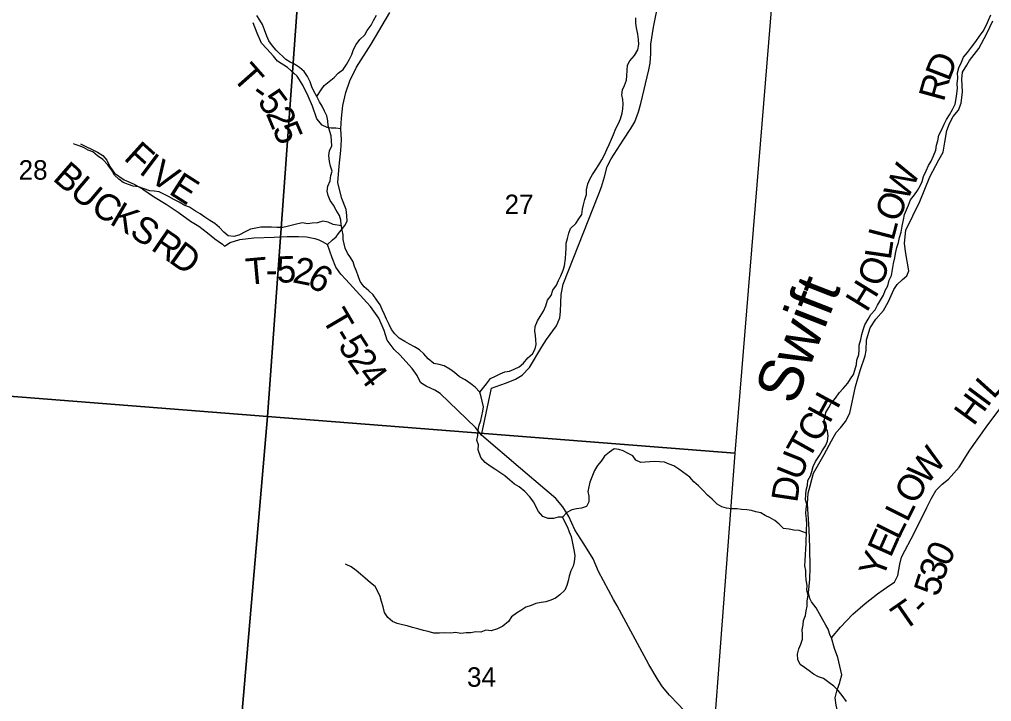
# Model space of a CAD drawing. Extents: x 1578669 to 1989827, y 208020 to 553079.
# Drawn here: x 1870195 to 1881237, y 380354 to 388101 of the extents above; entities that cross this region are included whole.
import ezdxf

# ---------------------------------------------------------------- set-up
doc = ezdxf.new("R2010")
doc.units = 0
for name, color, linetype in [('GM_X_Minor_River', 7, 'Continuous'), ('GM_X_Minor_River_Text', 7, 'Continuous'), ('GM_X_Section', 7, 'Continuous'), ('GM_X_Section_Text', 7, 'Continuous'), ('GM_X_State_Route', 7, 'Continuous'), ('GM_X_Township_Road', 7, 'Continuous'), ('GM_X_Township_Road_Text', 7, 'Continuous')]:
    doc.layers.add(name, color=color, linetype=linetype)

msp = doc.modelspace()

# ---------------------------------------------------------------- linework, layer by layer
at = {"layer": 'GM_X_Minor_River'}
for points in [[(1873498, 387392), (1873466, 387454), (1873428, 387508), (1873376, 387556), (1873320, 387592), (1873270, 387614), (1873220, 387646), (1873113, 387752), (1873071, 387802), (1873027, 387856), (1873005, 387910), (1872977, 387982), (1872957, 388042), (1872927, 388094), (1872891, 388146)], [(1873574, 387224), (1873622, 387300), (1873658, 387352), (1873714, 387394), (1873770, 387440), (1873816, 387490), (1873872, 387533), (1873911, 387589), (1873943, 387649), (1873971, 387703), (1873991, 387759), (1874021, 387815), (1874063, 387871), (1874119, 387925), (1874146, 387976), (1874190, 388034), (1874218, 388090), (1874250, 388150)], [(1879149, 382863), (1879179, 382917), (1879197, 382967), (1879211, 383023), (1879237, 383079), (1879283, 383147), (1879315, 383200), (1879350, 383258), (1879372, 383312), (1879380, 383372), (1879372, 383426), (1879346, 383482), (1879334, 383534), (1879346, 383588), (1879356, 383638), (1879389, 383694), (1879415, 383744), (1879463, 383801), (1879505, 383859), (1879551, 383909), (1879605, 383969), (1879635, 384019), (1879670, 384069), (1879684, 384119), (1879702, 384180), (1879706, 384232), (1879728, 384296), (1879732, 384346), (1879732, 384402), (1879752, 384464), (1879765, 384522), (1879779, 384576), (1879797, 384634), (1879837, 384695), (1879867, 384749), (1879917, 384801), (1879943, 384857), (1879975, 384911), (1880008, 384969), (1880030, 385021), (1880058, 385077), (1880076, 385138), (1880100, 385194), (1880114, 385262), (1880124, 385328), (1880137, 385394), (1880145, 385444), (1880161, 385510), (1880181, 385566), (1880191, 385624), (1880211, 385685), (1880223, 385753), (1880238, 385823), (1880250, 385887), (1880272, 385937), (1880294, 385993), (1880318, 386053), (1880362, 386107), (1880396, 386158), (1880428, 386212), (1880449, 386262), (1880463, 386318), (1880493, 386382), (1880521, 386442), (1880551, 386492), (1880579, 386550), (1880605, 386615), (1880612, 386671), (1880628, 386723), (1880640, 386787), (1880674, 386851), (1880700, 386911), (1880724, 386965), (1880760, 387019), (1880793, 387078), (1880823, 387138), (1880837, 387202), (1880843, 387254), (1880849, 387320), (1880845, 387370), (1880853, 387434), (1880849, 387496), (1880866, 387552), (1880894, 387614), (1880920, 387671), (1880964, 387725), (1881008, 387785), (1881060, 387849), (1881102, 387911), (1881141, 387967), (1881181, 388038), (1881201, 388094), (1881229, 388154)], [(1875423, 383868), (1875499, 383964), (1875544, 384022), (1875602, 384051), (1875654, 384075), (1875708, 384097), (1875760, 384105), (1875814, 384127), (1875870, 384157), (1875922, 384197), (1875970, 384257), (1876024, 384304), (1876053, 384358), (1876063, 384410), (1876061, 384462), (1876057, 384512), (1876051, 384562), (1876055, 384614), (1876079, 384678), (1876111, 384728), (1876148, 384789), (1876174, 384849), (1876192, 384913), (1876234, 384967), (1876254, 385027), (1876294, 385083), (1876318, 385137), (1876344, 385189), (1876373, 385252), (1876387, 385302), (1876397, 385386), (1876403, 385446), (1876405, 385502), (1876405, 385558), (1876419, 385614), (1876436, 385672), (1876456, 385726), (1876514, 385785), (1876548, 385835), (1876584, 385887), (1876592, 385945), (1876602, 385995), (1876618, 386055), (1876635, 386111), (1876637, 386167), (1876653, 386235), (1876673, 386286), (1876703, 386340), (1876743, 386398), (1876775, 386448), (1876812, 386508), (1876842, 386562), (1876866, 386624), (1876892, 386682), (1876920, 386739), (1876942, 386793), (1876970, 386863), (1877000, 386917), (1877023, 386973), (1877043, 387035), (1877049, 387087), (1877051, 387137), (1877049, 387193), (1877037, 387245), (1877045, 387300), (1877067, 387352), (1877092, 387412), (1877096, 387462), (1877100, 387522), (1877102, 387580), (1877128, 387632), (1877182, 387690), (1877218, 387754), (1877231, 387817), (1877227, 387873), (1877219, 387935), (1877205, 388007), (1877197, 388057), (1877195, 388117)], [(1876365, 382449), (1876313, 382447), (1876262, 382433), (1876202, 382431), (1876142, 382455), (1876091, 382513), (1876063, 382563), (1876037, 382619), (1875987, 382681), (1875935, 382741), (1875871, 382791), (1875817, 382821), (1875767, 382867), (1875707, 382917), (1875651, 382955), (1875595, 382993), (1875541, 383029), (1875487, 383069), (1875436, 383127), (1875406, 383211), (1875410, 383269), (1875392, 383321), (1875402, 383375), (1875406, 383433), (1875412, 383483), (1875436, 383544), (1875449, 383598), (1875459, 383650), (1875465, 383700), (1875453, 383764), (1875439, 383816), (1875423, 383868), (1875373, 383924), (1875321, 383964), (1875259, 384008), (1875195, 384042), (1875138, 384090), (1875082, 384128), (1875020, 384166), (1874964, 384180), (1874902, 384194), (1874838, 384248), (1874788, 384302), (1874738, 384348), (1874682, 384382), (1874624, 384411), (1874572, 384443), (1874510, 384479), (1874458, 384529), (1874422, 384579), (1874396, 384635), (1874363, 384695), (1874343, 384748), (1874315, 384806), (1874293, 384860), (1874253, 384914), (1874213, 384972), (1874163, 385018), (1874109, 385064), (1874065, 385126), (1874041, 385190), (1874024, 385240), (1874002, 385296), (1873986, 385346), (1873956, 385396), (1873922, 385448), (1873894, 385502), (1873882, 385552), (1873872, 385602), (1873872, 385654), (1873862, 385706), (1873851, 385770), (1873845, 385822), (1873831, 385874), (1873793, 385936), (1873761, 385992), (1873725, 386046), (1873703, 386100), (1873691, 386152), (1873697, 386206), (1873726, 386267), (1873734, 386327), (1873748, 386379), (1873728, 386435), (1873718, 386489), (1873710, 386557), (1873718, 386609), (1873743, 386665), (1873741, 386721), (1873737, 386779), (1873719, 386829), (1873703, 386891), (1873699, 386949), (1873687, 387004), (1873659, 387060), (1873635, 387114), (1873604, 387164), (1873574, 387224), (1873538, 387286), (1873518, 387336), (1873498, 387392)], [(1873853, 385757), (1873757, 385772), (1873701, 385800), (1873643, 385808), (1873579, 385790), (1873521, 385788), (1873468, 385780), (1873412, 385791), (1873358, 385781), (1873238, 385749), (1873186, 385739), (1873120, 385737), (1873058, 385743), (1873002, 385743), (1872938, 385743), (1872880, 385732), (1872820, 385720), (1872768, 385694), (1872688, 385652), (1872632, 385634), (1872566, 385644), (1872516, 385684), (1872466, 385736), (1872416, 385782), (1872358, 385818), (1872302, 385856), (1872248, 385894), (1872196, 385924), (1872128, 385968), (1872074, 385988), (1872008, 386025), (1871948, 386055), (1871888, 386089), (1871783, 386141), (1871727, 386151), (1871676, 386155), (1871599, 386181), (1871549, 386199), (1871485, 386209), (1871433, 386225), (1871375, 386249), (1871325, 386285), (1871273, 386331), (1871239, 386391), (1871199, 386451), (1871143, 386509), (1871081, 386553), (1871027, 386597), (1870975, 386617), (1870923, 386645), (1870873, 386666), (1870815, 386684), (1870809, 386692)], [(1879136, 382268), (1879053, 382298), (1878991, 382302), (1878939, 382310), (1878875, 382321), (1878825, 382369), (1878774, 382409), (1878724, 382441), (1878666, 382467), (1878616, 382499), (1878560, 382509), (1878510, 382523), (1878456, 382531), (1878398, 382535), (1878346, 382541), (1878284, 382543), (1878226, 382549), (1878174, 382565), (1878120, 382597), (1878062, 382651), (1878010, 382697), (1877962, 382749), (1877908, 382803), (1877854, 382851), (1877810, 382903), (1877686, 382994), (1877628, 383032), (1877574, 383050), (1877522, 383072), (1877464, 383078), (1877408, 383080), (1877356, 383076), (1877304, 383074), (1877252, 383068), (1877196, 383096), (1877162, 383146), (1877110, 383170), (1877054, 383200), (1877002, 383216), (1876950, 383224), (1876896, 383187), (1876840, 383139), (1876804, 383085), (1876760, 383035), (1876728, 382979), (1876696, 382901), (1876676, 382845), (1876661, 382792), (1876653, 382740), (1876663, 382686), (1876663, 382624), (1876637, 382570), (1876579, 382550), (1876523, 382544), (1876469, 382530), (1876411, 382502), (1876365, 382449), (1876392, 382391), (1876420, 382333), (1876438, 382283), (1876462, 382229), (1876472, 382171), (1876486, 382113), (1876498, 382059), (1876504, 382009), (1876497, 381941), (1876483, 381891), (1876459, 381837), (1876439, 381777), (1876429, 381724), (1876411, 381672), (1876389, 381620), (1876335, 381566), (1876283, 381528), (1876232, 381506), (1876176, 381488), (1876120, 381478), (1876060, 381467), (1876006, 381445), (1875948, 381427), (1875892, 381387), (1875840, 381359), (1875784, 381315), (1875750, 381265), (1875686, 381212), (1875625, 381178), (1875555, 381158), (1875491, 381164), (1875437, 381142), (1875381, 381146), (1875321, 381136), (1875269, 381134), (1875209, 381128), (1875147, 381139), (1875095, 381129), (1875021, 381133), (1874965, 381129), (1874901, 381131), (1874837, 381149), (1874785, 381161), (1874721, 381179)], [(1879591, 380354), (1879540, 380424), (1879494, 380478), (1879446, 380530), (1879388, 380572), (1879328, 380614), (1879270, 380636), (1879214, 380665), (1879164, 380701), (1879114, 380739), (1879062, 380775), (1879038, 380831), (1879032, 380892), (1879047, 380954), (1879069, 381006), (1879089, 381062), (1879089, 381118), (1879085, 381170), (1879099, 381226), (1879101, 381276), (1879123, 381332), (1879131, 381384), (1879142, 381439), (1879144, 381497), (1879154, 381563), (1879138, 381619), (1879142, 381673), (1879130, 381737), (1879128, 381791), (1879128, 381841), (1879117, 381897), (1879121, 381957), (1879125, 382019), (1879127, 382090), (1879133, 382144), (1879133, 382194), (1879137, 382254), (1879135, 382310), (1879138, 382364), (1879134, 382428), (1879128, 382488), (1879130, 382544), (1879138, 382594), (1879122, 382646), (1879126, 382704), (1879130, 382755), (1879147, 382811), (1879149, 382863)], [(1874721, 381179), (1874659, 381195), (1874599, 381215), (1874545, 381227), (1874485, 381241), (1874431, 381264), (1874379, 381310), (1874343, 381366), (1874327, 381429), (1874308, 381489), (1874294, 381547), (1874266, 381605), (1874234, 381659), (1874184, 381701), (1874122, 381757), (1874070, 381801), (1874020, 381841), (1873962, 381883), (1873908, 381911), (1873898, 381915)]]:
    msp.add_lwpolyline(points, dxfattribs=at)
at = {"layer": 'GM_X_Section'}
for points in [[(1873398, 388912), (1873014, 383593), (1867531, 384024), (1867957, 389311)], [(1878761, 388536), (1878321, 383175), (1873014, 383593), (1873398, 388912)], [(1867531, 384024), (1873014, 383593), (1872550, 378225), (1867563, 378586), (1867037, 378615)], [(1873014, 383593), (1878321, 383175), (1877916, 377814), (1873060, 378189), (1872550, 378225)]]:
    msp.add_lwpolyline(points, close=True, dxfattribs=at)
at = {"layer": 'GM_X_State_Route'}
for points in [[(1875963, 382938), (1875888, 383002), (1875444, 383381), (1875548, 383880), (1875559, 383912), (1875599, 383928), (1875728, 383974), (1875831, 384015), (1875905, 384062), (1875989, 384149), (1876130, 384384), (1876183, 384467), (1876296, 384622), (1876335, 384712), (1876342, 384782), (1876345, 384884), (1876347, 384978), (1876370, 385096), (1876777, 386121), (1876808, 386199), (1876839, 386315), (1876871, 386431), (1876916, 386516), (1877053, 386729), (1877141, 386862), (1877184, 386938), (1877226, 387050), (1877253, 387147), (1877343, 387529), (1877358, 387603), (1877367, 387713), (1877368, 387820), (1877399, 388012), (1877459, 388312)], [(1876983, 381441), (1876944, 381513), (1876771, 381830), (1876711, 381973), (1876607, 382147), (1876505, 382305), (1876437, 382456), (1876366, 382566), (1876287, 382661), (1875963, 382938)], [(1877669, 377626), (1877695, 377649), (1877825, 377764), (1877847, 377786), (1877872, 377820), (1877890, 377864), (1877907, 377930), (1878008, 379135), (1878044, 379428), (1878055, 379554), (1878043, 379685), (1878034, 379735), (1878022, 379785), (1877993, 379864), (1877945, 379961), (1877878, 380088), (1877792, 380204), (1877681, 380320), (1877580, 380427), (1877501, 380523), (1877452, 380595), (1877346, 380773), (1876983, 381441)]]:
    msp.add_lwpolyline(points, dxfattribs=at)
at = {"layer": 'GM_X_Township_Road'}
for points in [[(1875444, 383381), (1875376, 383468), (1874974, 383854), (1874914, 383891), (1874872, 383911), (1874816, 383935), (1874776, 383959), (1874752, 383979), (1874712, 384058), (1874657, 384136), (1874583, 384216), (1874519, 384289), (1874453, 384353), (1874371, 384460), (1874337, 384568), (1874276, 384708), (1874184, 384841), (1873904, 385147), (1873844, 385209), (1873788, 385289), (1873747, 385394), (1873693, 385546), (1873751, 385596), (1873791, 385630), (1873821, 385668), (1873864, 385726), (1873890, 385760), (1873918, 385808), (1873914, 385874), (1873906, 385944), (1873857, 386066), (1873827, 386183), (1873813, 386247), (1873826, 386433), (1873844, 386613), (1873855, 386732), (1873847, 386858), (1873855, 386980), (1873870, 387122), (1873904, 387270), (1873947, 387403), (1874025, 387557), (1874190, 387820), (1874402, 388178)], [(1873847, 386858), (1873789, 386866), (1873737, 386866), (1873689, 386875), (1873635, 386901), (1873573, 386973), (1873525, 387116), (1873473, 387230), (1873414, 387356), (1873348, 387455), (1873240, 387553), (1873126, 387626), (1873082, 387684), (1873006, 387765), (1872944, 387831), (1872894, 387943), (1872851, 388062)], [(1879513, 380572), (1879514, 380573), (1879519, 380588), (1879537, 380658), (1879492, 380854), (1879454, 380955), (1879420, 381077), (1879404, 381105), (1879380, 381177), (1879356, 381223), (1879320, 381282), (1879283, 381350), (1879245, 381418), (1879191, 381487), (1879173, 381525), (1879157, 381587), (1879172, 381743), (1879176, 381873), (1879173, 382104), (1879167, 382308), (1879148, 382601), (1879156, 382721), (1879175, 382805), (1879213, 382947), (1879336, 383161), (1879420, 383315), (1879473, 383409), (1879521, 383461), (1879579, 383533), (1879626, 383631), (1879691, 383931), (1879745, 384114), (1879800, 384282), (1879812, 384342), (1879818, 384462), (1879859, 384598), (1879923, 384696), (1880008, 384796), (1880066, 384898), (1880129, 385032), (1880167, 385092), (1880225, 385148), (1880275, 385188), (1880298, 385244), (1880280, 385354), (1880260, 385466), (1880248, 385561), (1880263, 385707), (1880422, 386033), (1880537, 386313), (1880640, 386507), (1880686, 386593), (1880708, 386705), (1880729, 386841), (1880761, 386917), (1880801, 386997), (1880860, 387069), (1880892, 387151), (1880908, 387277), (1880901, 387422), (1880907, 387500), (1880955, 387580), (1880988, 387634), (1881092, 387770), (1881183, 387940), (1881251, 388084)], [(1870887, 386688), (1871083, 386595), (1871143, 386557), (1871189, 386501), (1871223, 386429), (1871273, 386356), (1871385, 386280), (1871497, 386231), (1871595, 386173), (1871717, 386090), (1871863, 386004), (1871999, 385911), (1872139, 385808), (1872233, 385752), (1872333, 385679), (1872415, 385609), (1872453, 385582)], [(1872453, 385582), (1872454, 385582), (1872501, 385548), (1872523, 385526), (1872589, 385568), (1872697, 385602), (1872858, 385619), (1873090, 385628), (1873236, 385634), (1873365, 385637), (1873457, 385631), (1873549, 385613), (1873595, 385597), (1873635, 385580), (1873693, 385546)], [(1879420, 381077), (1879521, 381199), (1879661, 381347), (1879802, 381468), (1879940, 381578), (1880007, 381624), (1880081, 381674), (1880133, 381710), (1880173, 381786), (1880196, 381914), (1880216, 381992), (1880361, 382272), (1880502, 382556), (1880551, 382658), (1880609, 382756), (1880675, 382822), (1880750, 382878), (1880868, 383014), (1880989, 383209), (1881176, 383469), (1881341, 383695)], [(1878008, 379135), (1878254, 379111), (1878405, 379093), (1878525, 379088), (1878629, 379082), (1878727, 379095), (1878920, 379189), (1879155, 379344), (1879291, 379450), (1879426, 379564), (1879504, 379688), (1879539, 379808), (1879561, 379930), (1879545, 380046), (1879500, 380199), (1879474, 380313), (1879460, 380397), (1879484, 380488), (1879513, 380572)]]:
    msp.add_lwpolyline(points, dxfattribs=at)

# ---------------------------------------------------------------- texts
at = {"layer": 'GM_X_Minor_River_Text'}
msp.add_text('Swift', height=499.9, rotation=68.7407, dxfattribs=at).set_placement((1879001, 383706))
at = {"layer": 'GM_X_Section_Text'}
for s, p in [('28', (1870186, 386281)), ('27', (1875706, 385890)), ('34', (1875279, 380522))]:
    msp.add_text(s, height=221, rotation=0, dxfattribs=at).set_placement(p)
at = {"layer": 'GM_X_Township_Road_Text'}
for s, rotation, p in [('D', 68.9008, (1880756, 387386)), ('T', 311.3794, (1872602, 387438)), ('R', 74.61, (1880694, 387156)), ('-', 324.4266, (1872806, 387220)), ('5', 306.974, (1872889, 387165)), ('2', 292.6615, (1872990, 387034)), ('5', 293.5146, (1873063, 386859)), ('F', 317.8871, (1871368, 386516)), ('B', 319.03, (1870561, 386283)), ('I', 323.1388, (1871541, 386361)), ('V', 326.6084, (1871655, 386276)), ('W', 65.7914, (1880277, 386024)), ('U', 319.7193, (1870750, 386119)), ('E', 327.3993, (1871879, 386128)), ('C', 327.7932, (1870989, 385921)), ('O', 67.0296, (1880174, 385782)), ('K', 329.6679, (1871207, 385784)), ('S', 326.6236, (1871431, 385653)), ('R', 325.7178, (1871676, 385492)), ('L', 75.4711, (1880122, 385576)), ('D', 324.2929, (1871878, 385354)), ('L', 81.6748, (1880091, 385362)), ('T', 5.158, (1872778, 385085)), ('5', 1.8842, (1873120, 385109)), ('2', 348.638, (1873287, 385117)), ('O', 70.2798, (1879986, 385051)), ('6', 329.4289, (1873443, 385090)), ('-', 2.0298, (1872997, 385105)), ('H', 58.5271, (1879819, 384765)), ('T', 300.4529, (1873622, 384706)), ('-', 301.0723, (1873738, 384510)), ('5', 302.6695, (1873806, 384397)), ('2', 304.7696, (1873912, 384231)), ('4', 307.1559, (1874026, 384068)), ('L', 48.0711, (1881257, 383779)), ('H', 61.5941, (1879397, 383501)), ('H', 53.9067, (1881033, 383473)), ('I', 53.3861, (1881188, 383685)), ('C', 59.6742, (1879267, 383279)), ('T', 60.8122, (1879158, 383085)), ('W', 51.0109, (1880498, 382799)), ('U', 68.2121, (1879065, 382849)), ('D', 81.4959, (1879030, 382605)), ('O', 61.5041, (1880380, 382579)), ('L', 63.4004, (1880281, 382380)), ('E', 65.9348, (1880091, 381978)), ('L', 63.6592, (1880181, 382180)), ('Y', 69.5556, (1880001, 381735)), ('0', 63.5141, (1880742, 381874)), ('3', 71.7724, (1880689, 381709)), ('5', 72.5496, (1880633, 381534)), ('T', 34.761, (1880236, 381148)), ('-', 44.7623, (1880464, 381313))]:
    msp.add_text(s, height=300, rotation=rotation, dxfattribs=at).set_placement(p)

doc.saveas('drawing.dxf')
